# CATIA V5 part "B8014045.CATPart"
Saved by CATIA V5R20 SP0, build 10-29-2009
Part number: B8014045
Revision: 6
Definition: design
Nomenclature: B8014045
Source: made
Description: NOT SPECIFIED
Bounding box of the stored display mesh (mm): x -33 to 33, y -33 to 33, z 0 to 45
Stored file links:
  C:\Users\Utente\Desktop\3D files B801\B8014045.CATPart
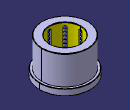
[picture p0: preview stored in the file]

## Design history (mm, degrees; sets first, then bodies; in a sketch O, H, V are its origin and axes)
Body1 "MANIFOLD_SOLID_BREP #38" (main body)
  Solid1: solid without history
Body2 "MANIFOLD_SOLID_BREP #76"
  Solid2: solid without history
Body3 "MANIFOLD_SOLID_BREP #114"
  Solid3: solid without history
Body4 "MANIFOLD_SOLID_BREP #152"
  Solid4: solid without history
Body5 "MANIFOLD_SOLID_BREP #190"
  Solid5: solid without history
Body6 "MANIFOLD_SOLID_BREP #228"
  Solid6: solid without history
Body7 "MANIFOLD_SOLID_BREP #266"
  Solid7: solid without history
Body8 "MANIFOLD_SOLID_BREP #304"
  Solid8: solid without history
Body9 "MANIFOLD_SOLID_BREP #342"
  Solid9: solid without history
Body10 "MANIFOLD_SOLID_BREP #2292"
  Solid10: solid without history
Body11 "MANIFOLD_SOLID_BREP #2330"
  Solid11: solid without history
Body12 "MANIFOLD_SOLID_BREP #2368"
  Solid12: solid without history
Body13 "MANIFOLD_SOLID_BREP #2406"
  Solid13: solid without history
Body14 "MANIFOLD_SOLID_BREP #2444"
  Solid14: solid without history
Body15 "MANIFOLD_SOLID_BREP #2482"
  Solid15: solid without history
Body16 "MANIFOLD_SOLID_BREP #2520"
  Solid16: solid without history
Body17 "MANIFOLD_SOLID_BREP #2558"
  Solid17: solid without history
Body18 "MANIFOLD_SOLID_BREP #2596"
  Solid18: solid without history
Body19 "MANIFOLD_SOLID_BREP #2634"
  Solid19: solid without history
Body20 "MANIFOLD_SOLID_BREP #2672"
  Solid20: solid without history
Body21 "MANIFOLD_SOLID_BREP #2710"
  Solid21: solid without history
Body22 "MANIFOLD_SOLID_BREP #2748"
  Solid22: solid without history
Body23 "MANIFOLD_SOLID_BREP #2786"
  Solid23: solid without history
Body24 "MANIFOLD_SOLID_BREP #2824"
  Solid24: solid without history
Body25 "MANIFOLD_SOLID_BREP #2862"
  Solid25: solid without history
Body26 "MANIFOLD_SOLID_BREP #2900"
  Solid26: solid without history
Body27 "MANIFOLD_SOLID_BREP #2938"
  Solid27: solid without history
Body28 "MANIFOLD_SOLID_BREP #2976"
  Solid28: solid without history
Body29 "MANIFOLD_SOLID_BREP #3014"
  Solid29: solid without history
Body30 "MANIFOLD_SOLID_BREP #3052"
  Solid30: solid without history
Body31 "MANIFOLD_SOLID_BREP #3090"
  Solid31: solid without history
Body32 "MANIFOLD_SOLID_BREP #3128"
  Solid32: solid without history
Body33 "MANIFOLD_SOLID_BREP #3166"
  Solid33: solid without history
Body34 "MANIFOLD_SOLID_BREP #3204"
  Solid34: solid without history
Body35 "MANIFOLD_SOLID_BREP #3242"
  Solid35: solid without history
Body36 "MANIFOLD_SOLID_BREP #3280"
  Solid36: solid without history
Body37 "MANIFOLD_SOLID_BREP #3318"
  Solid37: solid without history
Body38 "MANIFOLD_SOLID_BREP #3356"
  Solid38: solid without history
Body39 "MANIFOLD_SOLID_BREP #3394"
  Solid39: solid without history
Body40 "MANIFOLD_SOLID_BREP #3432"
  Solid40: solid without history
Body41 "MANIFOLD_SOLID_BREP #3470"
  Solid41: solid without history
Body42 "MANIFOLD_SOLID_BREP #3508"
  Solid42: solid without history
Body43 "MANIFOLD_SOLID_BREP #3546"
  Solid43: solid without history
Body44 "MANIFOLD_SOLID_BREP #3584"
  Solid44: solid without history
Body45 "MANIFOLD_SOLID_BREP #3622"
  Solid45: solid without history
Body46 "MANIFOLD_SOLID_BREP #3660"
  Solid46: solid without history
Body47 "MANIFOLD_SOLID_BREP #3698"
  Solid47: solid without history
Body48 "MANIFOLD_SOLID_BREP #3736"
  Solid48: solid without history
Body49 "MANIFOLD_SOLID_BREP #3774"
  Solid49: solid without history
Body50 "MANIFOLD_SOLID_BREP #3812"
  Solid50: solid without history
Body51 "MANIFOLD_SOLID_BREP #3850"
  Solid51: solid without history
Body52 "MANIFOLD_SOLID_BREP #3888"
  Solid52: solid without history
Body53 "MANIFOLD_SOLID_BREP #3926"
  Solid53: solid without history
Body54 "MANIFOLD_SOLID_BREP #3964"
  Solid54: solid without history
Body55 "MANIFOLD_SOLID_BREP #4002"
  Solid55: solid without history
Body56 "MANIFOLD_SOLID_BREP #4040"
  Solid56: solid without history
Body57 "MANIFOLD_SOLID_BREP #4078"
  Solid57: solid without history
Body58 "MANIFOLD_SOLID_BREP #4116"
  Solid58: solid without history
Body59 "MANIFOLD_SOLID_BREP #4154"
  Solid59: solid without history
Body60 "MANIFOLD_SOLID_BREP #4192"
  Solid60: solid without history
Body61 "MANIFOLD_SOLID_BREP #4230"
  Solid61: solid without history
Body62 "MANIFOLD_SOLID_BREP #4268"
  Solid62: solid without history
Body63 "MANIFOLD_SOLID_BREP #4306"
  Solid63: solid without history
Body64 "MANIFOLD_SOLID_BREP #4344"
  Solid64: solid without history
Body65 "MANIFOLD_SOLID_BREP #4382"
  Solid65: solid without history
Body66 "MANIFOLD_SOLID_BREP #4420"
  Solid66: solid without history
Body67 "MANIFOLD_SOLID_BREP #4458"
  Solid67: solid without history
Body68 "MANIFOLD_SOLID_BREP #4496"
  Solid68: solid without history
Body69 "MANIFOLD_SOLID_BREP #4534"
  Solid69: solid without history
Body70 "MANIFOLD_SOLID_BREP #4572"
  Solid70: solid without history
Body71 "MANIFOLD_SOLID_BREP #4610"
  Solid71: solid without history
Body72 "MANIFOLD_SOLID_BREP #4648"
  Solid72: solid without history
Body73 "MANIFOLD_SOLID_BREP #4686"
  Solid73: solid without history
